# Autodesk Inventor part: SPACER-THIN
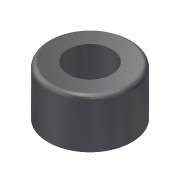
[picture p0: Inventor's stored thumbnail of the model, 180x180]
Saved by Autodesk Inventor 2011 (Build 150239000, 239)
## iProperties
Created: 2007-08
Part Number: SPACER-THIN
Material: Delrin, Black
Document SubType Name: Modeling
Density: 1.425 g/cm^3
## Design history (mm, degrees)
feature "Base1"
body "Solid1"
